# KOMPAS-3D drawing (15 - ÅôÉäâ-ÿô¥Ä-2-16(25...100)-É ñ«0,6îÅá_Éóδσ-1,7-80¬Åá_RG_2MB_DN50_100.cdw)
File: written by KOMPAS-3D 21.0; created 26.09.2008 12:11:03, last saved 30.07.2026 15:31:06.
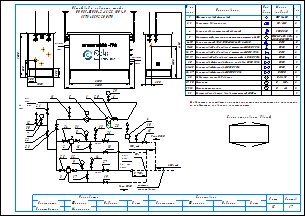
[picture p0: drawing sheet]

Sheets 1-2: A3, landscape

Document properties: Наименование: Макро:21; Автор: RaskoAdmin; Форматы листов документа: 2xA3; Полное имя файла: \\ur38nt01\Departments\КТО\КБ ПУРДГ\Заявки\Прайс-лист на типовые шкафы ГРПШ\ПУРДГ_стандарт_30_04_2026\ПУРДГ с RG_2MB\ПУРДГ-ШУЭО-2-16(25...100)-Р до0,6МПа_Рвых-1,7-80кПа_RG_2MB_DN50_100.cdw

Title block, sheet 1: Наименование: Пункт учета газа / ПУГ-Ш-400-Р / ЛГТИ.485922.001ТУ; designation: ЛГТИ.03.4411141; sheet number: 1; Количество листов документа: 2; organisation: ООО "ЭЛЬСТЕР Газэлектроника"; Форматы листов документа: A3; stored path: C:\Рабочие документы\Компас\ПУГ\Схема.cdw; Разработал: Устинов; Проверил: Кошкин; Утвердил: Кошкин
Title block, sheet 2: sheet number: 2; stored path: D:\Рабочие документы\Заявки\ПУРДГ\ПУРДГ-ШУЭО-2-100-Р 4411220.cdw; designation, second copy: ЛГТИ.03.4411141-

Views: Вид 1, Вид 2
Referenced files: wcvoit.frw
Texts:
  Normal
  № на
  схеме
  Усл.
  обозн.
  Марка
  (модель)
  Кол.
  Фильтр газовый фланцевый
  ФГ 16-50
  Регулятор давления газа
  RG/2MB
  Клапан предохранительный сбросной
  КПС DN20
  Измерительный комплекс с ротационным счетчиком Ду50
  СГ-ЭК-Р-(0,2...2,0)-
  Кран кнопочный VE-РАСКО-НЗ-1,6-G1/2-М20
  DN15
  Кран шаровой "под приварку" штуцерный DN20 PN16
  DN20
  Кран шаровой "под приварку" штуцерный DN15 PN16
  Кран шаровой "под приварку" штуцерный п/п DN20 PN16
  Кран шаровой фланцевый с мех. приводом DN50 PN16
  Кран шаровой фланцевый DN50 PN16
  Кран шаровой фланцевый DN100 PN16
  DN50
  DN100
  Индикатор перепада давления
  Манометр
  Манометр-напоромер
  Электрообогреватель взрывозащищенный 400Вт
  Delta 15
  0...     МПа
  0...     кПа
  Общий вид и габариты шкафа
  ПУРДГ-ШУЭО-2-16(25...100)-Р
  Выход газа
  Вход газа
  logo-rasko-ge.png
  DN 1
  местное
  сопротивление
  Римп DN20
  Выход
  газа
  Р=     кПа
  Вход
  Р=       МПа
  PDI
  Схема открывания дверей
  Предприятие изготовитель может заменять комплектующие на аналогичные,
  не ухудшающие заявленных характеристик.
  Должность
  Конструктор
  Фамилия
  Подпись
  Дата
  Согласовано
  Максимкин
  Лист
  Листов
  POLYLINE_STYLE_0.18_RGB_0_0_0
  POLYLINE_STYLE_0.50_RGB_0_0_0
  POLYLINE_STYLE_0.34_RGB_0_0_0
  PHANTOM_RGB_0_0_0_SC_1_THICK_0.18
  K5LT_THIN_RGB_0_0_0_THICK_0.18
  K5LT32769_RGB_0_0_0_THICK_0.18
  K5LT12_RGB_0_0_0_SC_1_THICK_0.18
  K5LT_DASHED_RGB_0_0_0_SC_1_THICK_0.18
  ACISOTGL_RGB_0_0_0_SC_0.8_THICK_0.25
  CONTINUOUS_RGB_0_127_31_THICK_0.3
  CONTINUOUS_RGB_0_0_255_THICK_0.35
  CONTINUOUS_RGB_255_0_0_THICK_0.35
  POLYLINE_STYLE_0.25_RGB_0_0_0
  CONTINUOUS_RGB_0_0_0_THICK_0.5
  POLYLINE_STYLE_0.35_RGB_0_0_255
  CONTINUOUS_RGB_0_0_0_THICK_0.4
  CONTINUOUS_RGB_0_0_0_THICK_0.35
  НЕВИДИМАЯ_RGB_0_0_0_SC_0.3_THICK_0.25
  СONTINUOUS_RGB_0_0_0_THICK_0.25
  ОСЕВАЯ2_RGB_248_153_30_SC_0.3_THICK_0.25
  Без оформления
Dimensions and other numbers on the sheet: 1; 2, 3; 2; 4; 5; 6-10; 11-15; 16, 17; 18, 19; 20; 21-25; 26, 27; 28; 29, 30; 31, 32; 33; 1500; 250; 300; 1050; 550; 305; 2300; 4130; 2000; 2600; 5,,,7DN 1; 7; 30; 12; 21; 22; 23; 11; 6; 29; 24; 31; 8; 16; 13; 26; 18; 10; 15; 25; 32; 9; 3; 17; 14; 27; 19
